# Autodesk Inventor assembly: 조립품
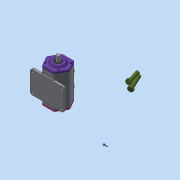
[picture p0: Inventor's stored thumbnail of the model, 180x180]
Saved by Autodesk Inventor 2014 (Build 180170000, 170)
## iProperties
Created: 2021-06
Part Number: 조립품
Document SubType Name: Assembly
Designer: net
Author: net
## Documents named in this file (11)
- C:\Users\net\Desktop\710606V1040\조립품.iam
- C:\Users\net\Desktop\710606V1040\본체.ipt
- C:\Users\net\Desktop\710606V1040\뒷커버.ipt
- C:\Users\net\Desktop\710606V1040\베어링 6203.ipt
- C:\Users\net\Desktop\710606V1040\베어링 6302.ipt
- C:\Users\net\Desktop\710606V1040\볼트 M4.ipt
- C:\Users\net\Desktop\710606V1040\부시.ipt
- C:\Users\net\Desktop\710606V1040\슬라이더.ipt
- C:\Users\net\Desktop\710606V1040\앞커버.ipt
- C:\Users\net\Desktop\710606V1040\오일실.ipt
- C:\Users\net\Desktop\710606V1040\편심축.ipt
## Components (3 placed, 3 different names)
1. 7-베어링 6203:1
2. 9-M4-소켓머리:1
3. 8-오일실:1
